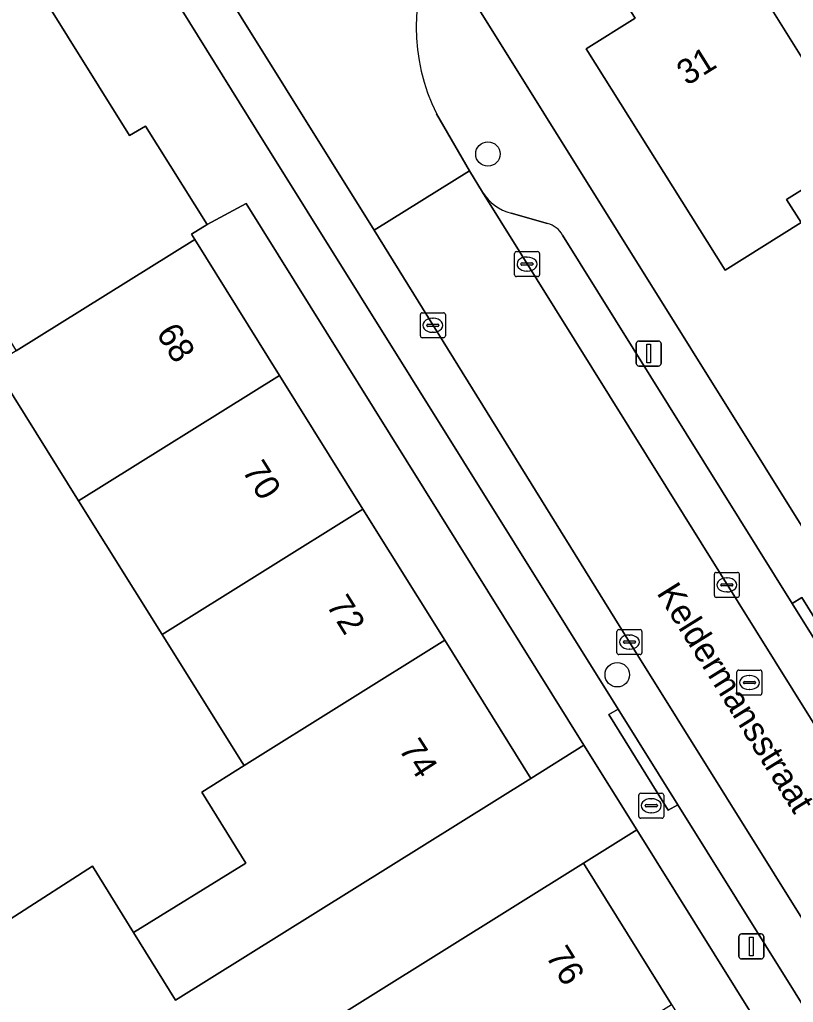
# Model space of a CAD drawing. Extents: x 159664 to 160323, y 385312 to 386115.
# Drawn here: x 159874.95 to 159905.94, y 385650.87 to 385690.2 of the extents above; entities that cross this region are included whole.
import ezdxf

# ---------------------------------------------------------------- set-up
doc = ezdxf.new("R2010")
doc.units = 0
for name, color, linetype in [('IMGEO_Boom', 7, 'Continuous'), ('IMGEO_Brandkraan', 7, 'Continuous'), ('IMGEO_Erf', 7, 'Continuous'), ('IMGEO_Kolk', 7, 'Continuous'), ('IMGEO_Lichtmast', 7, 'Continuous'), ('IMGEO_Openbare_ruimte_label', 7, 'Continuous'), ('IMGEO_Pand', 7, 'Continuous'), ('IMGEO_Pand_nummerreeks', 7, 'Continuous'), ('IMGEO_Parkeervlak_open', 7, 'Continuous'), ('IMGEO_Rijbaan_lokaal_open', 7, 'Continuous'), ('IMGEO_Rioolput', 7, 'Continuous'), ('IMGEO_Voetpad_open', 7, 'Continuous')]:
    doc.layers.add(name, color=color, linetype=linetype)

msp = doc.modelspace()

# ---------------------------------------------------------------- linework, layer by layer
at = {"layer": 'IMGEO_Boom'}
for centre in [(159893.707, 385684.824), (159898.886, 385663.979)]:
    msp.add_circle(centre, 0.489, dxfattribs=at)
at = {"layer": 'IMGEO_Brandkraan'}
for p, q in [((159899.75, 385658.311), (159899.75, 385659.163)), ((159899.825, 385659.237), (159900.677, 385659.237)), ((159900.238, 385659.017), (159900.263, 385659.017)), ((159900.751, 385659.163), (159900.751, 385658.311)), ((159900.009, 385658.731), (159900.009, 385658.743)), ((159900.447, 385658.694), (159900.049, 385658.694)), ((159900.052, 385658.78), (159900.45, 385658.78)), ((159900.493, 385658.743), (159900.493, 385658.731)), ((159900.677, 385658.237), (159899.825, 385658.237)), ((159900.261, 385658.457), (159900.236, 385658.457))]:
    msp.add_line(p, q, dxfattribs=at)
for points in [[(159899.75, 385658.311), (159899.75, 385659.163)], [(159899.825, 385659.237), (159900.677, 385659.237)], [(159900.751, 385659.163), (159900.751, 385658.311)], [(159900.677, 385658.237), (159899.825, 385658.237)]]:
    msp.add_lwpolyline(points, dxfattribs=at)
for centre, radius, start, end in [((159899.827, 385659.161), 0.0765, 91.552, 178.448), ((159899.827, 385659.161), 0.0765, 91.552, 178.448), ((159900.675, 385659.161), 0.0765, 1.552, 88.448), ((159900.675, 385659.161), 0.0765, 1.552, 88.448), ((159900.049, 385658.74), 0.0403, 85.8775, 175.7526), ((159900.046, 385658.73), 0.0366, 178.938, 274.7102), ((159900.45, 385658.737), 0.043, 264.8664, 352.4533), ((159900.454, 385658.742), 0.0386, 1.7309, 96.639), ((159899.827, 385658.313), 0.0765, 181.552, 268.448), ((159899.827, 385658.313), 0.0765, 181.552, 268.448), ((159900.675, 385658.313), 0.0765, 271.552, 358.448), ((159900.675, 385658.313), 0.0765, 271.552, 358.448)]:
    msp.add_arc(centre, radius, start, end, dxfattribs=at)
for centre, major_axis, ratio, start_param, end_param in [((159900.237, 385658.737), (-0.387, 0.002), 0.722429, 4.712389, 7.853982), ((159900.262, 385658.737), (-0.39, 0.002), 0.717154, 1.570796, 4.712389)]:
    msp.add_ellipse(centre, major_axis=major_axis, ratio=ratio, start_param=start_param, end_param=end_param, dxfattribs=at)
at = {"layer": 'IMGEO_Erf'}
for points in [[(159936.129, 385687.279), (159936.441, 385687.525), (159938.494, 385686.688), (159951.131, 385694.707), (159949.374, 385697.586), (159952.048, 385699.251), (159953.83, 385696.387), (159956.019, 385697.802), (159941.362, 385721.273), (159893.04, 385691.134), (159907.72, 385667.621), (159910.098, 385669.105), (159908.312, 385671.967), (159911.014, 385673.653), (159912.798, 385670.792), (159925.528, 385678.743), (159925.447, 385680.771), (159925.927, 385681.072), (159927.941, 385680.117), (159936.195, 385685.412)], [(159884.023, 385682.836), (159882.47, 385682.008), (159881.838, 385681.61), (159881.965, 385681.407), (159885.364, 385675.961), (159888.704, 385670.609), (159891.982, 385665.357), (159895.43, 385659.832), (159897.553, 385661.156)]]:
    msp.add_lwpolyline(points, close=True, dxfattribs=at)
for points in [[(159908.661, 385684.874), (159905.668, 385683.008), (159906.247, 385682.083), (159903.204, 385680.177), (159897.636, 385689.031), (159899.599, 385690.255), (159898.836, 385691.476), (159902.944, 385694.043), (159905.601, 385695.704), (159906.789, 385695.407)], [(159871.635, 385652.309), (159877.872, 385656.316), (159879.517, 385653.66), (159884.006, 385656.441), (159882.248, 385659.281), (159883.944, 385660.34), (159883.836, 385660.512), (159880.661, 385665.589), (159877.314, 385670.937), (159873.908, 385676.378)], [(159946.596, 385582.567), (159899.669, 385657.765), (159897.541, 385656.437), (159901.066, 385650.785), (159904.21, 385645.744), (159904.322, 385645.564), (159904.916, 385645.935), (159908.271, 385640.569)]]:
    msp.add_lwpolyline(points, dxfattribs=at)
at = {"layer": 'IMGEO_Kolk'}
for p, q in [((159894.772, 385679.992), (159894.772, 385680.844)), ((159894.847, 385680.918), (159895.699, 385680.918)), ((159895.26, 385680.698), (159895.285, 385680.698)), ((159895.773, 385680.844), (159895.773, 385679.992)), ((159895.031, 385680.412), (159895.031, 385680.424)), ((159895.469, 385680.375), (159895.071, 385680.375)), ((159895.074, 385680.461), (159895.472, 385680.461)), ((159895.515, 385680.424), (159895.515, 385680.412)), ((159895.699, 385679.918), (159894.847, 385679.918)), ((159895.283, 385680.138), (159895.258, 385680.138)), ((159891.001, 385677.541), (159891.001, 385678.393)), ((159891.076, 385678.467), (159891.928, 385678.467)), ((159892.002, 385678.393), (159892.002, 385677.541)), ((159891.26, 385677.961), (159891.26, 385677.973)), ((159891.698, 385677.924), (159891.3, 385677.924)), ((159891.303, 385678.01), (159891.701, 385678.01)), ((159891.489, 385678.247), (159891.514, 385678.247)), ((159891.744, 385677.973), (159891.744, 385677.961)), ((159891.512, 385677.687), (159891.487, 385677.687)), ((159891.928, 385677.467), (159891.076, 385677.467)), ((159902.85, 385668.075), (159903.702, 385668.075)), ((159902.775, 385667.149), (159902.775, 385668.001)), ((159903.263, 385667.855), (159903.288, 385667.855)), ((159903.776, 385668.001), (159903.776, 385667.149)), ((159903.034, 385667.569), (159903.034, 385667.581)), ((159903.472, 385667.532), (159903.074, 385667.532)), ((159903.077, 385667.618), (159903.475, 385667.618)), ((159903.286, 385667.295), (159903.261, 385667.295)), ((159903.518, 385667.581), (159903.518, 385667.569)), ((159903.702, 385667.075), (159902.85, 385667.075)), ((159898.874, 385664.862), (159898.874, 385665.714)), ((159898.949, 385665.788), (159899.801, 385665.788)), ((159899.875, 385665.714), (159899.875, 385664.862)), ((159899.176, 385665.331), (159899.574, 385665.331)), ((159899.362, 385665.568), (159899.387, 385665.568)), ((159899.133, 385665.282), (159899.133, 385665.294)), ((159899.571, 385665.245), (159899.173, 385665.245)), ((159899.385, 385665.008), (159899.36, 385665.008)), ((159899.617, 385665.294), (159899.617, 385665.282)), ((159899.801, 385664.788), (159898.949, 385664.788))]:
    msp.add_line(p, q, dxfattribs=at)
for points in [[(159894.772, 385679.992), (159894.772, 385680.844)], [(159894.847, 385680.918), (159895.699, 385680.918)], [(159895.773, 385680.844), (159895.773, 385679.992)], [(159895.699, 385679.918), (159894.847, 385679.918)], [(159891.001, 385677.541), (159891.001, 385678.393)], [(159891.076, 385678.467), (159891.928, 385678.467)], [(159892.002, 385678.393), (159892.002, 385677.541)], [(159891.928, 385677.467), (159891.076, 385677.467)], [(159902.85, 385668.075), (159903.702, 385668.075)], [(159902.775, 385667.149), (159902.775, 385668.001)], [(159903.776, 385668.001), (159903.776, 385667.149)], [(159903.702, 385667.075), (159902.85, 385667.075)], [(159898.874, 385664.862), (159898.874, 385665.714)], [(159898.949, 385665.788), (159899.801, 385665.788)], [(159899.875, 385665.714), (159899.875, 385664.862)], [(159899.801, 385664.788), (159898.949, 385664.788)]]:
    msp.add_lwpolyline(points, dxfattribs=at)
for centre, radius, start, end in [((159894.849, 385680.842), 0.0765, 91.552, 178.448), ((159894.849, 385680.842), 0.0765, 91.552, 178.448), ((159895.697, 385680.842), 0.0765, 1.552, 88.448), ((159895.697, 385680.842), 0.0765, 1.552, 88.448), ((159895.071, 385680.421), 0.0403, 85.8775, 175.7526), ((159895.068, 385680.411), 0.0366, 178.938, 274.7102), ((159895.472, 385680.418), 0.043, 264.8664, 352.4533), ((159895.476, 385680.423), 0.0386, 1.7309, 96.639), ((159894.849, 385679.994), 0.0765, 181.552, 268.448), ((159894.849, 385679.994), 0.0765, 181.552, 268.448), ((159895.697, 385679.994), 0.0765, 271.552, 358.448), ((159895.697, 385679.994), 0.0765, 271.552, 358.448), ((159891.078, 385678.391), 0.0765, 91.552, 178.448), ((159891.078, 385678.391), 0.0765, 91.552, 178.448), ((159891.926, 385678.391), 0.0765, 1.552, 88.448), ((159891.926, 385678.391), 0.0765, 1.552, 88.448), ((159891.3, 385677.97), 0.0403, 85.8775, 175.7526), ((159891.297, 385677.96), 0.0366, 178.938, 274.7102), ((159891.701, 385677.967), 0.043, 264.8664, 352.4533), ((159891.705, 385677.972), 0.0386, 1.7309, 96.639), ((159891.078, 385677.543), 0.0765, 181.552, 268.448), ((159891.078, 385677.543), 0.0765, 181.552, 268.448), ((159891.926, 385677.543), 0.0765, 271.552, 358.448), ((159891.926, 385677.543), 0.0765, 271.552, 358.448), ((159902.852, 385667.999), 0.0765, 91.552, 178.448), ((159902.852, 385667.999), 0.0765, 91.552, 178.448), ((159903.7, 385667.999), 0.0765, 1.552, 88.448), ((159903.7, 385667.999), 0.0765, 1.552, 88.448), ((159903.074, 385667.578), 0.0403, 85.8775, 175.7526), ((159903.071, 385667.568), 0.0366, 178.938, 274.7102), ((159903.475, 385667.575), 0.043, 264.8664, 352.4533), ((159903.479, 385667.58), 0.0386, 1.7309, 96.639), ((159902.852, 385667.151), 0.0765, 181.552, 268.448), ((159902.852, 385667.151), 0.0765, 181.552, 268.448), ((159903.7, 385667.151), 0.0765, 271.552, 358.448), ((159903.7, 385667.151), 0.0765, 271.552, 358.448), ((159898.951, 385665.712), 0.0765, 91.552, 178.448), ((159898.951, 385665.712), 0.0765, 91.552, 178.448), ((159899.799, 385665.712), 0.0765, 1.552, 88.448), ((159899.799, 385665.712), 0.0765, 1.552, 88.448), ((159899.173, 385665.291), 0.0403, 85.8775, 175.7526), ((159899.578, 385665.293), 0.0386, 1.7309, 96.639), ((159899.17, 385665.281), 0.0366, 178.938, 274.7102), ((159899.574, 385665.288), 0.043, 264.8664, 352.4533), ((159898.951, 385664.864), 0.0765, 181.552, 268.448), ((159898.951, 385664.864), 0.0765, 181.552, 268.448), ((159899.799, 385664.864), 0.0765, 271.552, 358.448), ((159899.799, 385664.864), 0.0765, 271.552, 358.448)]:
    msp.add_arc(centre, radius, start, end, dxfattribs=at)
for centre, major_axis, ratio, start_param, end_param in [((159895.259, 385680.418), (-0.387, 0.002), 0.722429, 4.712389, 7.853982), ((159895.284, 385680.418), (-0.39, 0.002), 0.717154, 1.570796, 4.712389), ((159891.488, 385677.967), (-0.387, 0.002), 0.722429, 4.712389, 7.853982), ((159891.513, 385677.967), (-0.39, 0.002), 0.717154, 1.570796, 4.712389), ((159903.262, 385667.575), (-0.387, 0.002), 0.722429, 4.712389, 7.853982), ((159903.287, 385667.575), (-0.39, 0.002), 0.717154, 1.570796, 4.712389), ((159899.361, 385665.288), (-0.387, 0.002), 0.722429, 4.712389, 7.853982), ((159899.386, 385665.288), (-0.39, 0.002), 0.717154, 1.570796, 4.712389)]:
    msp.add_ellipse(centre, major_axis=major_axis, ratio=ratio, start_param=start_param, end_param=end_param, dxfattribs=at)
at = {"layer": 'IMGEO_Lichtmast'}
for p, q in [((159899.649, 385676.437), (159899.649, 385677.237)), ((159899.649, 385677.237), (159899.649, 385676.437)), ((159899.749, 385677.337), (159900.539, 385677.337)), ((159900.539, 385677.337), (159899.749, 385677.337)), ((159900.639, 385677.237), (159900.639, 385676.437)), ((159900.639, 385676.437), (159900.639, 385677.237)), ((159900.539, 385676.337), (159899.749, 385676.337)), ((159899.749, 385676.337), (159900.539, 385676.337)), ((159903.761, 385652.705), (159903.761, 385653.505)), ((159903.761, 385653.505), (159903.761, 385652.705)), ((159903.861, 385653.605), (159904.651, 385653.605)), ((159904.651, 385653.605), (159903.861, 385653.605)), ((159904.751, 385653.505), (159904.751, 385652.705)), ((159904.751, 385652.705), (159904.751, 385653.505)), ((159904.651, 385652.605), (159903.861, 385652.605)), ((159903.861, 385652.605), (159904.651, 385652.605))]:
    msp.add_line(p, q, dxfattribs=at)
for points in [[(159900.069, 385677.212), (159900.219, 385677.212), (159900.219, 385676.462), (159900.069, 385676.462), (159900.069, 385677.212)], [(159904.181, 385653.48), (159904.331, 385653.48), (159904.331, 385652.73), (159904.181, 385652.73), (159904.181, 385653.48)]]:
    msp.add_lwpolyline(points, dxfattribs=at)
for centre, start, end in [((159899.749, 385677.237), 90, 180), ((159899.749, 385677.237), 90, 180), ((159900.539, 385677.237), 0, 90), ((159900.539, 385677.237), 360, 90), ((159899.749, 385676.437), 180, 270), ((159899.749, 385676.437), 180, 270), ((159900.539, 385676.437), 270, 0), ((159900.539, 385676.437), 270, 0), ((159903.861, 385653.505), 90, 180), ((159903.861, 385653.505), 90, 180), ((159904.651, 385653.505), 0, 90), ((159904.651, 385653.505), 360, 90), ((159903.861, 385652.705), 180, 270), ((159903.861, 385652.705), 180, 270), ((159904.651, 385652.705), 270, 0), ((159904.651, 385652.705), 270, 0)]:
    msp.add_arc(centre, 0.1, start, end, dxfattribs=at)
at = {"layer": 'IMGEO_Pand'}
for points in [[(159868.229, 385703.363), (159860.28, 385698.395), (159859.856, 385699.013), (159847.992, 385691.618), (159847.572, 385692.228), (159845.027, 385690.649), (159843.627, 385689.781), (159848.452, 385682.006), (159849.457, 385682.63), (159865.172, 385692.38), (159873.327, 385679.328), (159874.815, 385676.944), (159881.965, 385681.407), (159881.838, 385681.61), (159882.47, 385682.008), (159879.997, 385685.936), (159879.357, 385685.561)], [(159908.661, 385696.576), (159906.789, 385695.407), (159905.601, 385695.704), (159902.944, 385694.043), (159907.414, 385686.873), (159910.404, 385688.745), (159913.456, 385683.872), (159915.703, 385685.28)], [(159902.944, 385694.043), (159898.836, 385691.476), (159899.599, 385690.255), (159897.636, 385689.031), (159903.204, 385680.177), (159906.247, 385682.083), (159905.668, 385683.008), (159908.661, 385684.874), (159907.414, 385686.873)], [(159873.908, 385676.378), (159877.314, 385670.937), (159885.364, 385675.961), (159881.965, 385681.407), (159874.815, 385676.944)], [(159877.314, 385670.937), (159880.661, 385665.589), (159888.704, 385670.609), (159885.364, 385675.961)], [(159891.982, 385665.357), (159888.704, 385670.609), (159880.661, 385665.589), (159883.836, 385660.512), (159883.944, 385660.34)], [(159895.43, 385659.832), (159891.982, 385665.357), (159883.944, 385660.34), (159882.248, 385659.281), (159884.006, 385656.441), (159879.517, 385653.66), (159881.199, 385650.947)], [(159901.066, 385650.785), (159897.541, 385656.437), (159883.314, 385647.559), (159884.982, 385644.861), (159889.482, 385647.642), (159891.306, 385644.694), (159893.002, 385645.752)]]:
    msp.add_lwpolyline(points, close=True, dxfattribs=at)
at = {"layer": 'IMGEO_Parkeervlak_open'}
for points in [[(159962.17, 385564.73), (159961.779, 385565.383), (159924.478, 385625.1), (159922.547, 385628.192), (159899.375, 385665.288), (159889.146, 385681.776), (159876.656, 385701.792), (159875.092, 385700.818), (159884.424, 385685.806), (159898.925, 385662.608), (159901.313, 385658.777), (159948.098, 385583.838), (159950.488, 385580), (159958.964, 385566.45)], [(159893.484, 385683.297), (159926.401, 385630.553), (159928.296, 385627.517), (159965.594, 385567.755), (159965.967, 385567.159)], [(159896.098, 385682.045), (159894.636, 385682.45)], [(159965.875, 385570.728), (159957.4, 385584.281), (159955.023, 385588.111), (159908.276, 385663), (159905.898, 385666.829), (159896.695, 385681.58)]]:
    msp.add_lwpolyline(points, dxfattribs=at)
for centre, radius, start, end in [((159895.188, 385684.407), 2.034, 213.0938, 254.2564), ((159895.837, 385681.094), 0.986, 29.5113, 74.6591)]:
    msp.add_arc(centre, radius, start, end, dxfattribs=at)
at = {"layer": 'IMGEO_Rijbaan_lokaal_open'}
msp.add_lwpolyline([(159882.205, 385701.463), (159879.463, 385705.823), (159875.66, 385703.431), (159876.656, 385701.792), (159889.146, 385681.776), (159892.964, 385684.149), (159891.649, 385686.438)], dxfattribs=at)
msp.add_lwpolyline([(159893.484, 385683.297), (159892.964, 385684.149), (159889.146, 385681.776), (159899.375, 385665.288), (159922.547, 385628.192), (159926.401, 385630.553)], close=True, dxfattribs=at)
msp.add_arc((159898.601, 385689.902), 7.767, 153.5337, 206.4829, dxfattribs=at)
at = {"layer": 'IMGEO_Rioolput'}
for p, q in [((159903.754, 385664.167), (159904.606, 385664.167)), ((159903.679, 385663.241), (159903.679, 385664.093)), ((159904.167, 385663.947), (159904.192, 385663.947)), ((159904.68, 385664.093), (159904.68, 385663.241)), ((159903.938, 385663.661), (159903.938, 385663.673)), ((159904.376, 385663.624), (159903.978, 385663.624)), ((159903.981, 385663.71), (159904.379, 385663.71)), ((159904.19, 385663.387), (159904.165, 385663.387)), ((159904.422, 385663.673), (159904.422, 385663.661)), ((159904.606, 385663.167), (159903.754, 385663.167))]:
    msp.add_line(p, q, dxfattribs=at)
for points in [[(159903.754, 385664.167), (159904.606, 385664.167)], [(159903.679, 385663.241), (159903.679, 385664.093)], [(159904.68, 385664.093), (159904.68, 385663.241)], [(159904.606, 385663.167), (159903.754, 385663.167)]]:
    msp.add_lwpolyline(points, dxfattribs=at)
for centre, radius, start, end in [((159903.756, 385664.091), 0.0765, 91.552, 178.448), ((159903.756, 385664.091), 0.0765, 91.552, 178.448), ((159904.604, 385664.091), 0.0765, 1.552, 88.448), ((159904.604, 385664.091), 0.0765, 1.552, 88.448), ((159903.978, 385663.67), 0.0403, 85.8775, 175.7526), ((159903.975, 385663.66), 0.0366, 178.938, 274.7102), ((159904.379, 385663.667), 0.043, 264.8664, 352.4533), ((159904.383, 385663.672), 0.0386, 1.7309, 96.639), ((159903.756, 385663.243), 0.0765, 181.552, 268.448), ((159903.756, 385663.243), 0.0765, 181.552, 268.448), ((159904.604, 385663.243), 0.0765, 271.552, 358.448), ((159904.604, 385663.243), 0.0765, 271.552, 358.448)]:
    msp.add_arc(centre, radius, start, end, dxfattribs=at)
for centre, major_axis, ratio, start_param, end_param in [((159904.166, 385663.667), (-0.387, 0.002), 0.722429, 4.712389, 7.853982), ((159904.191, 385663.667), (-0.39, 0.002), 0.717154, 1.570796, 4.712389)]:
    msp.add_ellipse(centre, major_axis=major_axis, ratio=ratio, start_param=start_param, end_param=end_param, dxfattribs=at)
at = {"layer": 'IMGEO_Voetpad_open'}
for points in [[(159870.48, 385704.729), (159868.229, 385703.363), (159879.357, 385685.561), (159879.997, 385685.936), (159882.47, 385682.008), (159884.023, 385682.836), (159897.553, 385661.156), (159899.669, 385657.765), (159946.596, 385582.567), (159948.717, 385579.169), (159962.464, 385557.14), (159964.577, 385558.015)], [(159958.964, 385566.45), (159950.488, 385580), (159950.108, 385579.772), (159947.714, 385583.597), (159948.098, 385583.838), (159901.313, 385658.777), (159900.929, 385658.558), (159898.546, 385662.389), (159898.925, 385662.608), (159884.424, 385685.806), (159875.092, 385700.818)], [(159970.609, 385562.217), (159972.712, 385563.525), (159958.955, 385585.56), (159956.838, 385588.951), (159909.89, 385664.146), (159907.72, 385667.621), (159893.04, 385691.134)], [(159891.649, 385686.438), (159892.964, 385684.149), (159893.484, 385683.297)], [(159894.636, 385682.45), (159896.098, 385682.045)], [(159896.695, 385681.58), (159905.898, 385666.829), (159906.281, 385667.07), (159908.661, 385663.245), (159908.276, 385663), (159955.023, 385588.111), (159955.397, 385588.346), (159957.782, 385584.525), (159957.4, 385584.281), (159965.875, 385570.728)], [(159883.314, 385647.559), (159897.541, 385656.437), (159899.669, 385657.765), (159897.553, 385661.156), (159895.43, 385659.832), (159881.199, 385650.947), (159879.517, 385653.66), (159877.872, 385656.316), (159871.635, 385652.309)]]:
    msp.add_lwpolyline(points, dxfattribs=at)
for points in [[(159908.276, 385663), (159908.661, 385663.245), (159906.281, 385667.07), (159905.898, 385666.829)], [(159901.313, 385658.777), (159898.925, 385662.608), (159898.546, 385662.389), (159900.929, 385658.558)]]:
    msp.add_lwpolyline(points, close=True, dxfattribs=at)
for centre, radius, start, end in [((159898.601, 385689.902), 7.767, 153.5337, 206.4829), ((159895.188, 385684.407), 2.034, 213.0938, 254.2564), ((159895.837, 385681.094), 0.986, 29.5113, 74.6591)]:
    msp.add_arc(centre, radius, start, end, dxfattribs=at)

# ---------------------------------------------------------------- texts
at = {"layer": 'IMGEO_Openbare_ruimte_label'}
msp.add_text('Keldermansstraat', height=1, rotation=301.9265, dxfattribs=at).set_placement((159900.444, 385667.255))
at = {"layer": 'IMGEO_Pand_nummerreeks'}
for s, rotation, p in [('31', 32.0112, (159901.677, 385687.535)), ('68', 302.0633, (159880.398, 385677.644)), ('70', 302.0579, (159883.839, 385672.151)), ('72', 302.0568, (159887.211, 385666.767)), ('74', 302.7501, (159890.109, 385661.005)), ('76', 301.9651, (159895.997, 385652.718))]:
    msp.add_text(s, height=1, rotation=rotation, dxfattribs=at).set_placement(p)

doc.saveas('drawing.dxf')
